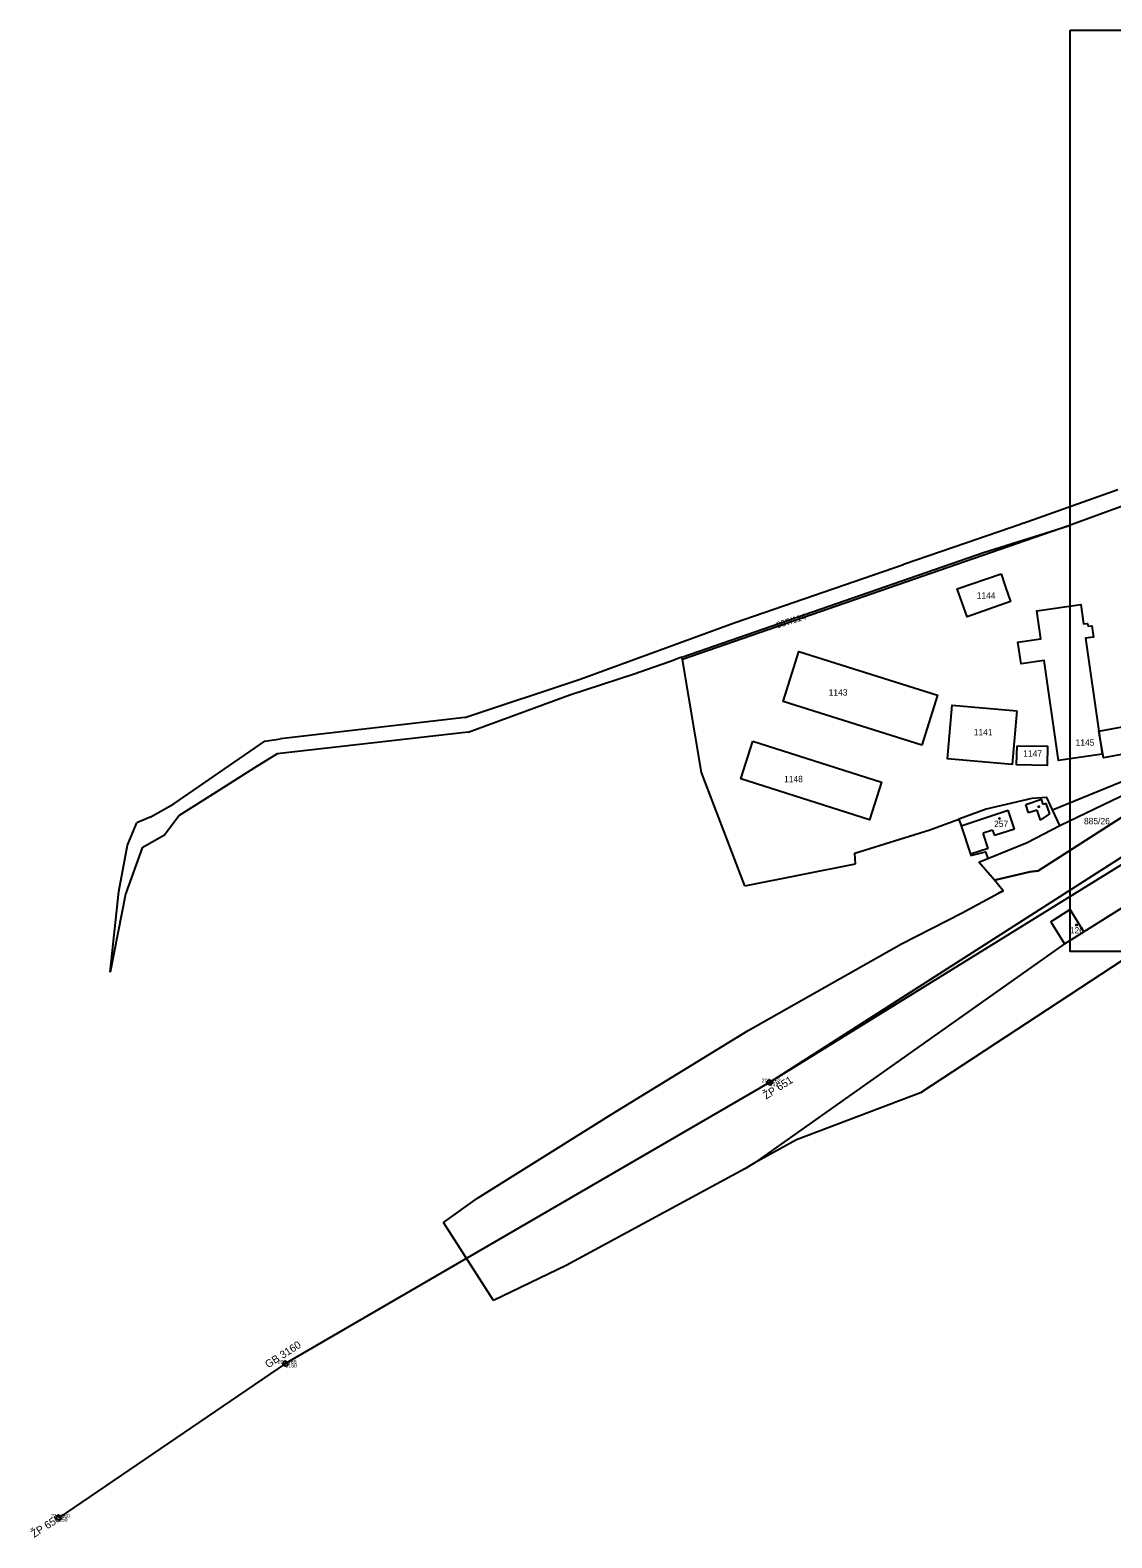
# Model space of a CAD drawing. Extents: x -752210 to -751291, y -1028374 to -1027785.
# Drawn here: x -752209.5 to -751867.6, y -1028373.9 to -1027897.6 of the extents above; entities that cross this region are included whole.
import ezdxf

# ---------------------------------------------------------------- set-up
doc = ezdxf.new("R2010")
doc.units = 0
for name, color, linetype in [('Vrstva 4', 7, 'Continuous'), ('Vrstva 53', 7, 'Continuous'), ('Vrstva 55', 7, 'Continuous'), ('Vrstva 56', 7, 'Continuous'), ('Vrstva 57', 7, 'Continuous'), ('Vrstva 59', 7, 'Continuous'), ('Vrstva 60', 7, 'Continuous'), ('Vrstva 61', 7, 'Continuous'), ('Vrstva 63', 7, 'Continuous')]:
    doc.layers.add(name, color=color, linetype=linetype)

msp = doc.modelspace()

# ---------------------------------------------------------------- linework, layer by layer
at = {"layer": 'Vrstva 4'}
msp.add_lwpolyline([(-751880.79, -1027897.6), (-751466.79, -1027897.6), (-751466.79, -1028188.6), (-751880.79, -1028188.6)], close=True, dxfattribs=at)
at = {"layer": 'Vrstva 53'}
for points in [[(-752078.91, -1028274.27), (-752068.08, -1028266.53), (-752030.45, -1028242.94), (-752025.93, -1028240.15), (-751982.6, -1028213.59), (-751934.1, -1028186.19), (-751914.9, -1028176.41), (-751903.43, -1028170.23), (-751901.96, -1028169.44), (-751904.77, -1028166.14), (-751893.52, -1028163.47), (-751890.97, -1028163.13), (-751806.75, -1028109.29)], [(-751864.36, -1028191.47), (-751928.16, -1028233.3), (-751967.27, -1028248.1), (-751980.73, -1028255.56), (-751983.66, -1028257.34), (-752040.12, -1028287.87), (-752063.02, -1028298.92)]]:
    msp.add_lwpolyline(points, dxfattribs=at)
at = {"layer": 'Vrstva 55'}
for p, q in [((-751895.64, -1028053.38), (-751865.7, -1028042.71)), ((-751859.41, -1028046.14), (-751881.38, -1028054.14)), ((-751881.38, -1028054.14), (-752003.38, -1028096.4)), ((-751896.64, -1028053.77), (-751913.74, -1028059.67)), ((-751895.64, -1028053.38), (-751896.64, -1028053.77)), ((-751913.74, -1028059.67), (-751933.45, -1028066.43)), ((-752003.56, -1028095.62), (-752005.66, -1028096.36)), ((-752003.38, -1028096.4), (-752003.56, -1028095.62)), ((-752072.09, -1028114.77), (-752130.41, -1028121.51)), ((-752138.59, -1028130.64), (-752150.71, -1028138.27)), ((-752171.57, -1028146.24), (-752175.83, -1028148.04)), ((-751884.03, -1028148.84), (-751886.38, -1028143.87)), ((-751983.58, -1028167.93), (-751948.62, -1028160.91)), ((-751909.62, -1028160.48), (-751906.85, -1028159.28)), ((-751904.77, -1028166.14), (-751909.62, -1028160.48)), ((-751893.52, -1028163.47), (-751904.77, -1028166.14)), ((-751901.96, -1028169.44), (-751904.77, -1028166.14)), ((-751901.96, -1028169.44), (-751903.43, -1028170.23)), ((-751861.84, -1028173.32), (-751876.44, -1028182.41)), ((-751882.55, -1028186.22), (-751876.44, -1028182.41)), ((-751882.55, -1028186.22), (-751980.73, -1028255.56)), ((-752030.45, -1028242.94), (-752025.93, -1028240.15)), ((-751980.73, -1028255.56), (-751983.66, -1028257.34)), ((-752063.02, -1028298.92), (-752078.91, -1028274.27))]:
    msp.add_line(p, q, dxfattribs=at)
for points in [[(-752003.56, -1028095.62), (-751908.15, -1028062.63), (-751881.38, -1028054.14)], [(-752072.09, -1028114.77), (-752035.67, -1028102.67), (-751987.04, -1028084.81), (-751933.45, -1028066.43)], [(-751902.66, -1028069.39), (-751901.2, -1028073.54), (-751899.62, -1028078.07), (-751913.4, -1028082.89), (-751916.47, -1028074.11), (-751911.88, -1028072.54), (-751902.66, -1028069.39)], [(-751750.57, -1028069.21), (-751798.29, -1028099.68), (-751808.53, -1028106.05), (-751806.75, -1028109.29), (-751890.97, -1028163.13), (-751893.52, -1028163.47)], [(-751884.03, -1028148.84), (-751854.09, -1028134.41), (-751824.25, -1028114.78), (-751751.51, -1028067.92)], [(-751871.76, -1028119), (-751870.71, -1028126.36), (-751884.51, -1028128.34), (-751889.05, -1028096.75), (-751896.33, -1028097.8), (-751897.36, -1028090.88), (-751890.04, -1028089.83), (-751891.29, -1028081.06), (-751877.43, -1028079.08), (-751876.57, -1028085.19), (-751875.28, -1028085.01), (-751875.15, -1028085.9), (-751873.96, -1028085.73), (-751873.45, -1028089.34), (-751875.93, -1028089.7), (-751871.76, -1028119)], [(-751927.67, -1028123.47), (-751971.5, -1028109.63), (-751966.53, -1028093.91), (-751922.77, -1028107.71), (-751927.67, -1028123.47)], [(-752071.11, -1028119.33), (-752038.95, -1028107.53), (-752018.63, -1028100.96), (-752005.66, -1028096.36)], [(-751983.58, -1028167.93), (-751997.32, -1028132.13), (-752003.38, -1028096.4)], [(-751897.63, -1028112.6), (-751899.12, -1028129.53), (-751919.55, -1028127.76), (-751918.08, -1028110.8), (-751897.63, -1028112.6)], [(-751886.38, -1028143.87), (-751862.7, -1028134.19), (-751839.92, -1028121.01), (-751825.11, -1028112.91)], [(-751871.76, -1028119), (-751855.74, -1028116.09), (-751854.37, -1028124.51), (-751870.23, -1028127.46), (-751871.76, -1028119)], [(-752171.57, -1028146.24), (-752164.12, -1028142.01), (-752135.34, -1028122.25), (-752130.41, -1028121.51)], [(-752071.11, -1028119.33), (-752131.47, -1028126.16), (-752138.59, -1028130.64)], [(-751981.1, -1028122.22), (-751940.47, -1028135.13), (-751944.23, -1028147.01), (-751984.89, -1028134.14), (-751981.1, -1028122.22)], [(-751897.58, -1028123.64), (-751887.96, -1028123.82), (-751888.1, -1028129.87), (-751897.72, -1028129.64), (-751897.58, -1028123.64)], [(-752150.71, -1028138.27), (-752162.4, -1028145.64), (-752167.07, -1028151.94)], [(-751886.38, -1028143.87), (-751888.21, -1028140.02), (-751892.91, -1028140.3), (-751907.34, -1028143.68), (-751915.97, -1028146.83)], [(-751948.62, -1028160.91), (-751948.85, -1028157.62), (-751925.12, -1028150.18), (-751915.97, -1028146.83)], [(-751915.97, -1028146.83), (-751915.28, -1028148.92), (-751912.32, -1028157.92), (-751912.2, -1028158.29)], [(-752184.23, -1028195.14), (-752181.48, -1028169.72), (-752178.76, -1028155.03), (-752175.83, -1028148.04)], [(-752167.07, -1028151.94), (-752174.15, -1028155.95), (-752179.37, -1028170.52), (-752184.23, -1028195.14)], [(-751906.85, -1028159.28), (-751894.37, -1028154.17), (-751884.03, -1028148.84)], [(-751912.2, -1028158.29), (-751907.54, -1028157.19), (-751906.85, -1028159.28)], [(-752025.93, -1028240.15), (-751982.6, -1028213.59), (-751934.1, -1028186.19), (-751914.9, -1028176.41), (-751903.43, -1028170.23)], [(-751837.73, -1028166.78), (-751864.36, -1028191.47), (-751928.16, -1028233.3), (-751967.27, -1028248.1), (-751980.73, -1028255.56)], [(-751876.44, -1028182.41), (-751880.8, -1028175.41), (-751886.93, -1028179.3), (-751882.55, -1028186.22)], [(-752078.91, -1028274.27), (-752068.08, -1028266.53), (-752030.45, -1028242.94)], [(-751983.66, -1028257.34), (-752040.12, -1028287.87), (-752063.02, -1028298.92)]]:
    msp.add_lwpolyline(points, dxfattribs=at)
at = {"layer": 'Vrstva 56'}
for p, q in [((-751894.85, -1028142.2), (-751889.87, -1028140.56)), ((-751893.98, -1028144.86), (-751894.85, -1028142.2)), ((-751889.34, -1028142.18), (-751889.87, -1028140.56)), ((-751888.34, -1028141.85), (-751889.34, -1028142.18)), ((-751887.25, -1028145.18), (-751888.34, -1028141.85)), ((-751915.28, -1028148.92), (-751900.38, -1028144.02)), ((-751898.43, -1028149.96), (-751900.38, -1028144.02)), ((-751891.22, -1028143.96), (-751893.98, -1028144.86)), ((-751890.18, -1028147.14), (-751891.22, -1028143.96)), ((-751890.18, -1028147.14), (-751887.25, -1028145.18)), ((-751905.3, -1028150.34), (-751908.27, -1028151.31)), ((-751906.7, -1028156.07), (-751908.27, -1028151.31)), ((-751905.3, -1028150.34), (-751904.74, -1028152.04)), ((-751898.43, -1028149.96), (-751904.74, -1028152.04)), ((-751906.7, -1028156.07), (-751912.32, -1028157.92))]:
    msp.add_line(p, q, dxfattribs=at)
at = {"layer": 'Vrstva 59'}
for centre in [(-751903.15, -1028146.63), (-751890.74, -1028142.88), (-751878.83, -1028180.29)]:
    msp.add_circle(centre, 0.175, dxfattribs=at)
at = {"layer": 'Vrstva 60'}
for p, q in [((-751975.84, -1028230), (-751975.84, -1028230)), ((-752128.84, -1028318.85), (-752128.84, -1028318.85)), ((-752200.48, -1028367.51), (-752200.48, -1028367.51))]:
    msp.add_line(p, q, dxfattribs=at)
at = {"layer": 'Vrstva 63'}
for p, q in [((-751551.77, -1027958.95), (-751975.84, -1028230)), ((-751715.69, -1028069.13), (-751975.84, -1028230)), ((-751975.84, -1028230), (-752128.84, -1028318.85)), ((-751975.88, -1028230.02), (-751975.8, -1028229.97)), ((-752128.84, -1028318.85), (-752200.48, -1028367.51)), ((-752128.88, -1028318.88), (-752128.8, -1028318.82)), ((-752200.52, -1028367.53), (-752200.43, -1028367.48))]:
    msp.add_line(p, q, dxfattribs=at)
for centre in [(-751975.84, -1028230), (-752128.84, -1028318.85), (-752200.48, -1028367.51)]:
    msp.add_circle(centre, 0.756, dxfattribs=at)

# ---------------------------------------------------------------- texts
at = {"layer": 'Vrstva 57'}
for s, p in [('1144', (-751910.34, -1028077.17)), ('1143', (-751957.14, -1028107.8)), ('1141', (-751911.28, -1028120.38)), ('1145', (-751879.09, -1028123.65)), ('1147', (-751895.65, -1028127.09)), ('1148', (-751971.24, -1028135.17)), ('885/26', (-751876.44, -1028148.44)), ('257', (-751904.85, -1028149.31)), ('126', (-751880.91, -1028182.95))]:
    msp.add_text(s, height=2, dxfattribs=at).set_placement(p)
msp.add_text('957/114', height=2, rotation=17.4652, dxfattribs=at).set_placement((-751973.3, -1028086.57))
at = {"layer": 'Vrstva 60'}
for s, p in [('651', (-751975.84, -1028231.2)), ('3160', (-752128.84, -1028320.05)), ('650', (-752200.48, -1028368.71))]:
    msp.add_text(s, height=1.2, dxfattribs=at).set_placement(p)
at = {"layer": 'Vrstva 61'}
for s, p in [('209.162', (-751978.29, -1028230)), ('209.486', (-752131.29, -1028318.85)), ('211.360', (-752202.93, -1028367.51))]:
    msp.add_text(s, height=1.2, dxfattribs=at).set_placement(p)
at = {"layer": 'Vrstva 63'}
for s, p in [('ŽP 651', (-751976.91, -1028235.45)), ('GB 3160', (-752134.32, -1028320.35)), ('ŽP 650', (-752208.29, -1028373.93))]:
    msp.add_text(s, height=2.4, rotation=32.6028, dxfattribs=at).set_placement(p)

doc.saveas('drawing.dxf')
